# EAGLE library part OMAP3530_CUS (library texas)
OMAP 3530/25 Applications Processor 600-MHz ARM Cortex?-A8 Core Auto generated by make-symbol-device-package-bsdl.ulp Rev. 23 Source: sprm314.bsd
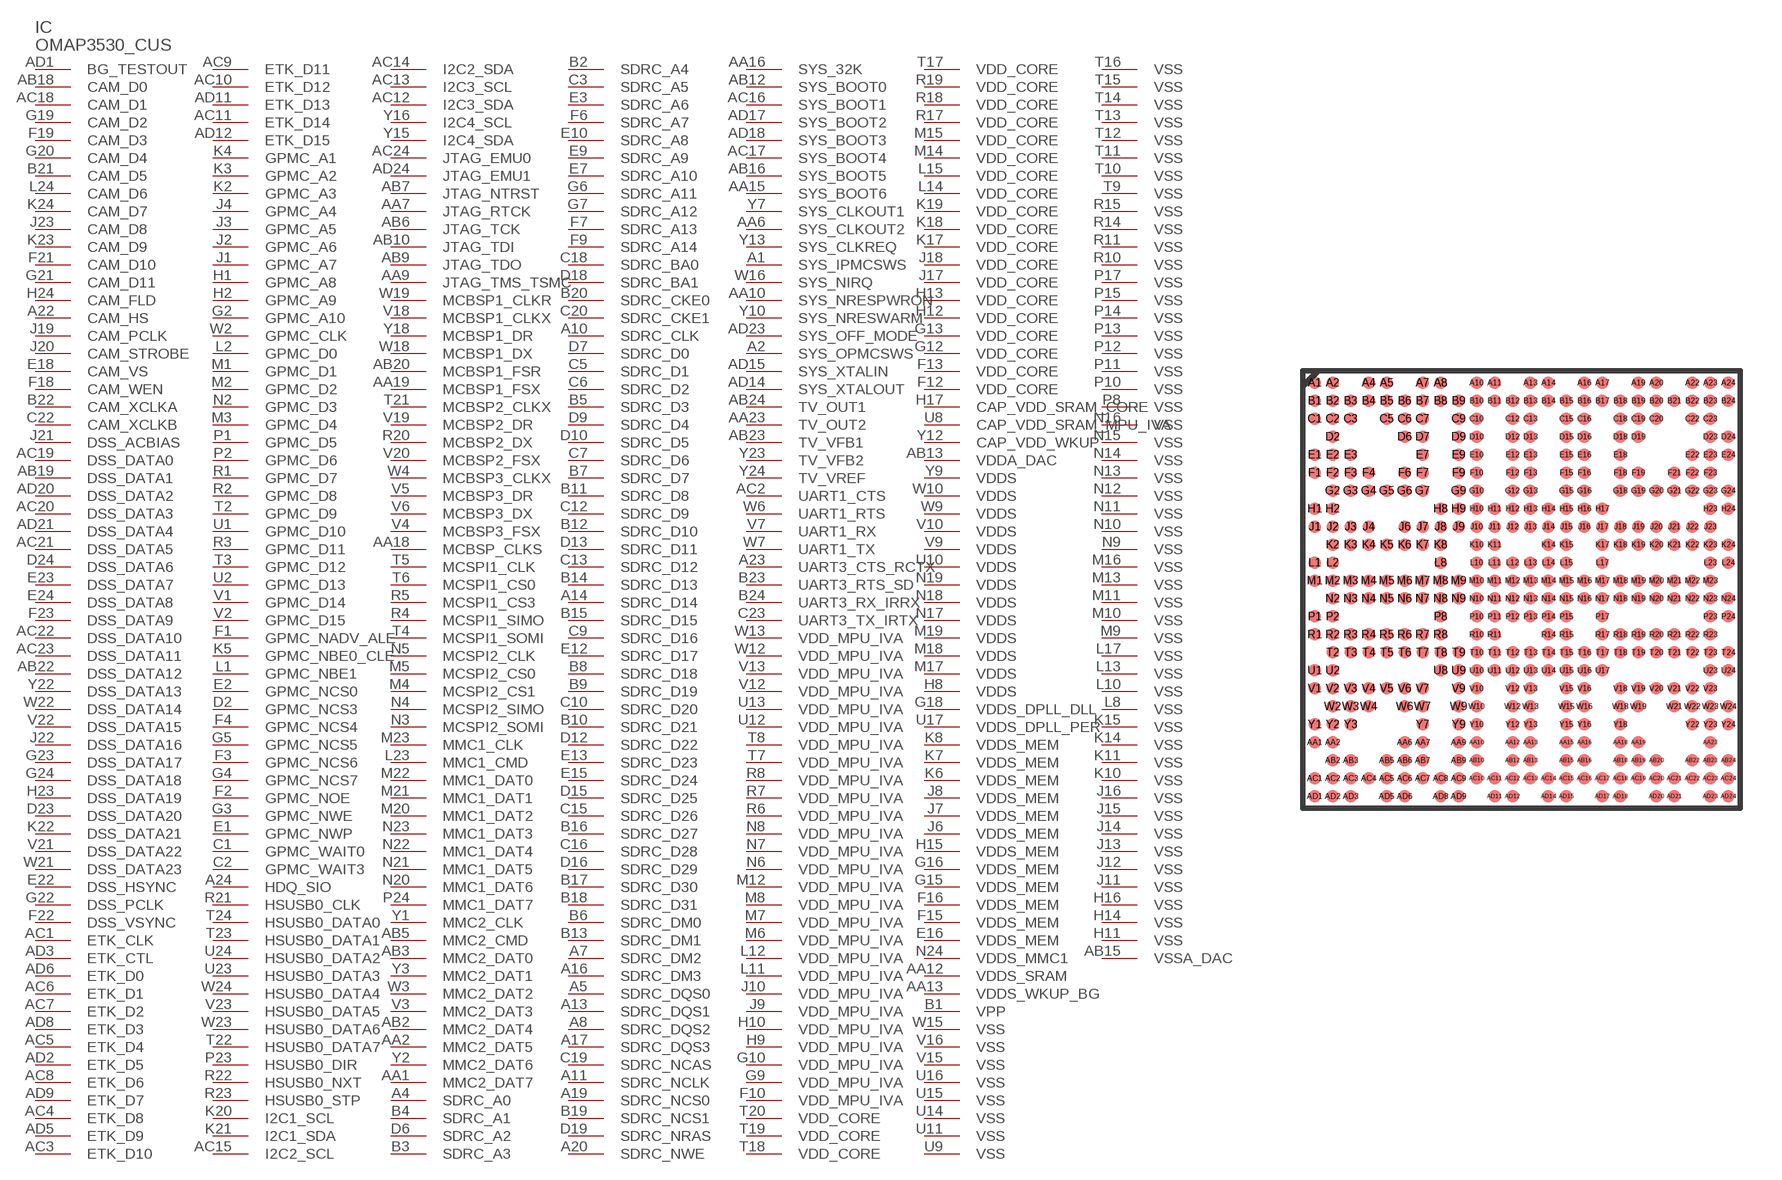
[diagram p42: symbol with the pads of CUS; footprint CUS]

Designator prefix IC

## OMAP3530_CUS (OC_FARNELL: unknown; OC_NEWARK: unknown)  [CUS]
A1  SYS_IPMCSWS  pas
A2  SYS_OPMCSWS  pas
A4  SDRC_A0  out
A5  SDRC_DQS0  pas
A7  SDRC_DM2  out
A8  SDRC_DQS2  pas
A10  SDRC_CLK  pas
A11  SDRC_NCLK  pas
A13  SDRC_DQS1  pas
A14  SDRC_D14
A16  SDRC_DM3  out
A17  SDRC_DQS3  pas
A19  SDRC_NCS0  out
A20  SDRC_NWE  out
A22  CAM_HS
A23  UART3_CTS_RCTX
A24  HDQ_SIO
AA1  MMC2_DAT7
AA2  MMC2_DAT5
AA6  SYS_CLKOUT2
AA7  JTAG_RTCK  pas
AA9  JTAG_TMS_TSMC  in
AA10  SYS_NRESPWRON  pas
AA12  VDDS_SRAM  pwr
AA13  VDDS_WKUP_BG  pwr
AA15  SYS_BOOT6
AA16  SYS_32K  pas
AA18  MCBSP_CLKS
AA19  MCBSP1_FSX
AA23  TV_OUT2  pas
AB2  MMC2_DAT4
AB3  MMC2_DAT0
AB5  MMC2_CMD
AB6  JTAG_TCK  in
AB7  JTAG_NTRST  in
AB9  JTAG_TDO  out
AB10  JTAG_TDI  in
AB12  SYS_BOOT0
AB13  VDDA_DAC  pwr
AB15  VSSA_DAC  pwr
AB16  SYS_BOOT5
AB18  CAM_D0
AB19  DSS_DATA1
AB20  MCBSP1_FSR
AB22  DSS_DATA12
AB23  TV_VFB1  pas
AB24  TV_OUT1  pas
AC1  ETK_CLK
AC2  UART1_CTS
AC3  ETK_D10
AC4  ETK_D8
AC5  ETK_D4
AC6  ETK_D1
AC7  ETK_D2
AC8  ETK_D6
AC9  ETK_D11
AC10  ETK_D12
AC11  ETK_D14
AC12  I2C3_SDA
AC13  I2C3_SCL
AC14  I2C2_SDA
AC15  I2C2_SCL
AC16  SYS_BOOT1
AC17  SYS_BOOT4
AC18  CAM_D1
AC19  DSS_DATA0
AC20  DSS_DATA3
AC21  DSS_DATA5
AC22  DSS_DATA10
AC23  DSS_DATA11
AC24  JTAG_EMU0  pas
AD1  BG_TESTOUT
AD2  ETK_D5
AD3  ETK_CTL
AD5  ETK_D9
AD6  ETK_D0
AD8  ETK_D3
AD9  ETK_D7
AD11  ETK_D13
AD12  ETK_D15
AD14  SYS_XTALOUT  pas
AD15  SYS_XTALIN  pas
AD17  SYS_BOOT2
AD18  SYS_BOOT3
AD20  DSS_DATA2
AD21  DSS_DATA4
AD23  SYS_OFF_MODE
AD24  JTAG_EMU1  pas
B1  VPP  pas
B2  SDRC_A4  out
B3  SDRC_A3  out
B4  SDRC_A1  out
B5  SDRC_D3
B6  SDRC_DM0  out
B7  SDRC_D7
B8  SDRC_D18
B9  SDRC_D19
B10  SDRC_D21
B11  SDRC_D8
B12  SDRC_D10
B13  SDRC_DM1  out
B14  SDRC_D13
B15  SDRC_D15
B16  SDRC_D27
B17  SDRC_D30
B18  SDRC_D31
B19  SDRC_NCS1  out
B20  SDRC_CKE0  out
B21  CAM_D5
B22  CAM_XCLKA
B23  UART3_RTS_SD
B24  UART3_RX_IRRX
C1  GPMC_WAIT0  in
C2  GPMC_WAIT3
C3  SDRC_A5  out
C5  SDRC_D1
C6  SDRC_D2
C7  SDRC_D6
C9  SDRC_D16
C10  SDRC_D20
C12  SDRC_D9
C13  SDRC_D12
C15  SDRC_D26
C16  SDRC_D28
C18  SDRC_BA0  out
C19  SDRC_NCAS  out
C20  SDRC_CKE1  out
C22  CAM_XCLKB
C23  UART3_TX_IRTX
D2  GPMC_NCS3
D6  SDRC_A2  out
D7  SDRC_D0
D9  SDRC_D4
D10  SDRC_D5
D12  SDRC_D22
D13  SDRC_D11
D15  SDRC_D25
D16  SDRC_D29
D18  SDRC_BA1  out
D19  SDRC_NRAS  out
D23  DSS_DATA20
D24  DSS_DATA6
E1  GPMC_NWP
E2  GPMC_NCS0  out
E3  SDRC_A6  out
E7  SDRC_A10  out
E9  SDRC_A9  out
E10  SDRC_A8  out
E12  SDRC_D17
E13  SDRC_D23
E15  SDRC_D24
E16  VDDS_MEM  pwr
E18  CAM_VS
E22  DSS_HSYNC
E23  DSS_DATA7
E24  DSS_DATA8
F1  GPMC_NADV_ALE  out
F2  GPMC_NOE  out
F3  GPMC_NCS6
F4  GPMC_NCS4
F6  SDRC_A7  out
F7  SDRC_A13  out
F9  SDRC_A14  out
F10  VDD_MPU_IVA  pwr
F12  VDD_CORE  pwr
F13  VDD_CORE  pwr
F15  VDDS_MEM  pwr
F16  VDDS_MEM  pwr
F18  CAM_WEN
F19  CAM_D3
F21  CAM_D10
F22  DSS_VSYNC
F23  DSS_DATA9
G2  GPMC_A10
G3  GPMC_NWE  out
G4  GPMC_NCS7
G5  GPMC_NCS5
G6  SDRC_A11  out
G7  SDRC_A12  out
G9  VDD_MPU_IVA  pwr
G10  VDD_MPU_IVA  pwr
G12  VDD_CORE  pwr
G13  VDD_CORE  pwr
G15  VDDS_MEM  pwr
G16  VDDS_MEM  pwr
G18  VDDS_DPLL_DLL  pwr
G19  CAM_D2
G20  CAM_D4
G21  CAM_D11
G22  DSS_PCLK
G23  DSS_DATA17
G24  DSS_DATA18
H1  GPMC_A8
H2  GPMC_A9
H8  VDDS  pwr
H9  VDD_MPU_IVA  pwr
H10  VDD_MPU_IVA  pwr
H11  VSS  pwr
H12  VDD_CORE  pwr
H13  VDD_CORE  pwr
H14  VSS  pwr
H15  VDDS_MEM  pwr
H16  VSS  pwr
H17  CAP_VDD_SRAM_CORE  pwr
H23  DSS_DATA19
H24  CAM_FLD
J1  GPMC_A7
J2  GPMC_A6
J3  GPMC_A5
J4  GPMC_A4
J6  VDDS_MEM  pwr
J7  VDDS_MEM  pwr
J8  VDDS_MEM  pwr
J9  VDD_MPU_IVA  pwr
J10  VDD_MPU_IVA  pwr
J11  VSS  pwr
J12  VSS  pwr
J13  VSS  pwr
J14  VSS  pwr
J15  VSS  pwr
J16  VSS  pwr
J17  VDD_CORE  pwr
J18  VDD_CORE  pwr
J19  CAM_PCLK
J20  CAM_STROBE
J21  DSS_ACBIAS
J22  DSS_DATA16
J23  CAM_D8
K2  GPMC_A3
K3  GPMC_A2
K4  GPMC_A1
K5  GPMC_NBE0_CLE
K6  VDDS_MEM  pwr
K7  VDDS_MEM  pwr
K8  VDDS_MEM  pwr
K10  VSS  pwr
K11  VSS  pwr
K14  VSS  pwr
K15  VSS  pwr
K17  VDD_CORE  pwr
K18  VDD_CORE  pwr
K19  VDD_CORE  pwr
K20  I2C1_SCL
K21  I2C1_SDA
K22  DSS_DATA21
K23  CAM_D9
K24  CAM_D7
L1  GPMC_NBE1
L2  GPMC_D0
L8  VSS  pwr
L10  VSS  pwr
L11  VDD_MPU_IVA  pwr
L12  VDD_MPU_IVA  pwr
L13  VSS  pwr
L14  VDD_CORE  pwr
L15  VDD_CORE  pwr
L17  VSS  pwr
L23  MMC1_CMD
L24  CAM_D6
M1  GPMC_D1
M2  GPMC_D2
M3  GPMC_D4
M4  MCSPI2_CS1
M5  MCSPI2_CS0
M6  VDD_MPU_IVA  pwr
M7  VDD_MPU_IVA  pwr
M8  VDD_MPU_IVA  pwr
M9  VSS  pwr
M10  VSS  pwr
M11  VSS  pwr
M12  VDD_MPU_IVA  pwr
M13  VSS  pwr
M14  VDD_CORE  pwr
M15  VDD_CORE  pwr
M16  VSS  pwr
M17  VDDS  pwr
M18  VDDS  pwr
M19  VDDS  pwr
M20  MMC1_DAT2
M21  MMC1_DAT1
M22  MMC1_DAT0
M23  MMC1_CLK
N2  GPMC_D3
N3  MCSPI2_SOMI
N4  MCSPI2_SIMO
N5  MCSPI2_CLK
N6  VDD_MPU_IVA  pwr
N7  VDD_MPU_IVA  pwr
N8  VDD_MPU_IVA  pwr
N9  VSS  pwr
N10  VSS  pwr
N11  VSS  pwr
N12  VSS  pwr
N13  VSS  pwr
N14  VSS  pwr
N15  VSS  pwr
N16  VSS  pwr
N17  VDDS  pwr
N18  VDDS  pwr
N19  VDDS  pwr
N20  MMC1_DAT6
N21  MMC1_DAT5
N22  MMC1_DAT4
N23  MMC1_DAT3
N24  VDDS_MMC1  pwr
P1  GPMC_D5
P2  GPMC_D6
P8  VSS  pwr
P10  VSS  pwr
P11  VSS  pwr
P12  VSS  pwr
P13  VSS  pwr
P14  VSS  pwr
P15  VSS  pwr
P17  VSS  pwr
P23  HSUSB0_DIR
P24  MMC1_DAT7
R1  GPMC_D7
R2  GPMC_D8
R3  GPMC_D11
R4  MCSPI1_SIMO
R5  MCSPI1_CS3
R6  VDD_MPU_IVA  pwr
R7  VDD_MPU_IVA  pwr
R8  VDD_MPU_IVA  pwr
R10  VSS  pwr
R11  VSS  pwr
R14  VSS  pwr
R15  VSS  pwr
R17  VDD_CORE  pwr
R18  VDD_CORE  pwr
R19  VDD_CORE  pwr
R20  MCBSP2_DX
R21  HSUSB0_CLK
R22  HSUSB0_NXT
R23  HSUSB0_STP
T2  GPMC_D9
T3  GPMC_D12
T4  MCSPI1_SOMI
T5  MCSPI1_CLK
T6  MCSPI1_CS0
T7  VDD_MPU_IVA  pwr
T8  VDD_MPU_IVA  pwr
T9  VSS  pwr
T10  VSS  pwr
T11  VSS  pwr
T12  VSS  pwr
T13  VSS  pwr
T14  VSS  pwr
T15  VSS  pwr
T16  VSS  pwr
T17  VDD_CORE  pwr
T18  VDD_CORE  pwr
T19  VDD_CORE  pwr
T20  VDD_CORE  pwr
T21  MCBSP2_CLKX
T22  HSUSB0_DATA7
T23  HSUSB0_DATA1
T24  HSUSB0_DATA0
U1  GPMC_D10
U2  GPMC_D13
U8  CAP_VDD_SRAM_MPU_IVA  pwr
U9  VSS  pwr
U10  VDDS  pwr
U11  VSS  pwr
U12  VDD_MPU_IVA  pwr
U13  VDD_MPU_IVA  pwr
U14  VSS  pwr
U15  VSS  pwr
U16  VSS  pwr
U17  VDDS_DPLL_PER  pwr
U23  HSUSB0_DATA3
U24  HSUSB0_DATA2
V1  GPMC_D14
V2  GPMC_D15
V3  MMC2_DAT3
V4  MCBSP3_FSX
V5  MCBSP3_DR
V6  MCBSP3_DX
V7  UART1_RX
V9  VDDS  pwr
V10  VDDS  pwr
V12  VDD_MPU_IVA  pwr
V13  VDD_MPU_IVA  pwr
V15  VSS  pwr
V16  VSS  pwr
V18  MCBSP1_CLKX
V19  MCBSP2_DR
V20  MCBSP2_FSX
V21  DSS_DATA22
V22  DSS_DATA15
V23  HSUSB0_DATA5
W2  GPMC_CLK
W3  MMC2_DAT2
W4  MCBSP3_CLKX
W6  UART1_RTS
W7  UART1_TX
W9  VDDS  pwr
W10  VDDS  pwr
W12  VDD_MPU_IVA  pwr
W13  VDD_MPU_IVA  pwr
W15  VSS  pwr
W16  SYS_NIRQ
W18  MCBSP1_DX
W19  MCBSP1_CLKR
W21  DSS_DATA23
W22  DSS_DATA14
W23  HSUSB0_DATA6
W24  HSUSB0_DATA4
Y1  MMC2_CLK
Y2  MMC2_DAT6
Y3  MMC2_DAT1
Y7  SYS_CLKOUT1
Y9  VDDS  pwr
Y10  SYS_NRESWARM  pas
Y12  CAP_VDD_WKUP  pwr
Y13  SYS_CLKREQ
Y15  I2C4_SDA
Y16  I2C4_SCL
Y18  MCBSP1_DR
Y22  DSS_DATA13
Y23  TV_VFB2  pas
Y24  TV_VREF  pas

## Footprint CUS (pad centres in mm)
CUS (S-PBGA-N423) Auto generated by make-symbol-device-package-bsdl.ulp Rev. 23 Source: sprm314.bsd
smd 0.45 x 0.45: A1 -7.475,7.475; A2 -6.825,7.475; A4 -5.525,7.475; A5 -4.875,7.475; A7 -3.575,7.475; A8 -2.925,7.475; A10 -1.625,7.475; A11 -0.975,7.475; A13 0.325,7.475; A14 0.975,7.475; A16 2.275,7.475; A17 2.925,7.475; A19 4.225,7.475; A20 4.875,7.475; A22 6.175,7.475; A23 6.825,7.475; A24 7.475,7.475; AA1 -7.475,-5.525; AA2 -6.825,-5.525; AA6 -4.225,-5.525; AA7 -3.575,-5.525; AA9 -2.275,-5.525; AA10 -1.625,-5.525; AA12 -0.325,-5.525; AA13 0.325,-5.525; AA15 1.625,-5.525; AA16 2.275,-5.525; AA18 3.575,-5.525; AA19 4.225,-5.525; AA23 6.825,-5.525; AB2 -6.825,-6.175; AB3 -6.175,-6.175; AB5 -4.875,-6.175; AB6 -4.225,-6.175; AB7 -3.575,-6.175; AB9 -2.275,-6.175; AB10 -1.625,-6.175; AB12 -0.325,-6.175; AB13 0.325,-6.175; AB15 1.625,-6.175; AB16 2.275,-6.175; AB18 3.575,-6.175; AB19 4.225,-6.175; AB20 4.875,-6.175; AB22 6.175,-6.175; AB23 6.825,-6.175; AB24 7.475,-6.175; AC1 -7.475,-6.825; AC2 -6.825,-6.825; AC3 -6.175,-6.825; AC4 -5.525,-6.825; AC5 -4.875,-6.825; AC6 -4.225,-6.825; AC7 -3.575,-6.825; AC8 -2.925,-6.825; AC9 -2.275,-6.825; AC10 -1.625,-6.825; AC11 -0.975,-6.825; AC12 -0.325,-6.825; AC13 0.325,-6.825; AC14 0.975,-6.825; AC15 1.625,-6.825; AC16 2.275,-6.825; AC17 2.925,-6.825; AC18 3.575,-6.825; AC19 4.225,-6.825; AC20 4.875,-6.825; AC21 5.525,-6.825; AC22 6.175,-6.825; AC23 6.825,-6.825; AC24 7.475,-6.825; AD1 -7.475,-7.475; AD2 -6.825,-7.475; AD3 -6.175,-7.475; AD5 -4.875,-7.475; AD6 -4.225,-7.475; AD8 -2.925,-7.475; AD9 -2.275,-7.475; AD11 -0.975,-7.475; AD12 -0.325,-7.475; AD14 0.975,-7.475; AD15 1.625,-7.475; AD17 2.925,-7.475; AD18 3.575,-7.475; AD20 4.875,-7.475; AD21 5.525,-7.475; AD23 6.825,-7.475; AD24 7.475,-7.475; B1 -7.475,6.825; B2 -6.825,6.825; B3 -6.175,6.825; B4 -5.525,6.825; B5 -4.875,6.825; B6 -4.225,6.825; B7 -3.575,6.825; B8 -2.925,6.825; B9 -2.275,6.825; B10 -1.625,6.825; B11 -0.975,6.825; B12 -0.325,6.825; B13 0.325,6.825; B14 0.975,6.825; B15 1.625,6.825; B16 2.275,6.825; B17 2.925,6.825; B18 3.575,6.825; B19 4.225,6.825; B20 4.875,6.825; B21 5.525,6.825; B22 6.175,6.825; B23 6.825,6.825; B24 7.475,6.825; C1 -7.475,6.175; C2 -6.825,6.175; C3 -6.175,6.175; C5 -4.875,6.175; C6 -4.225,6.175; C7 -3.575,6.175; C9 -2.275,6.175; C10 -1.625,6.175; C12 -0.325,6.175; C13 0.325,6.175; C15 1.625,6.175; C16 2.275,6.175; C18 3.575,6.175; C19 4.225,6.175; C20 4.875,6.175; C22 6.175,6.175; C23 6.825,6.175; D2 -6.825,5.525; D6 -4.225,5.525; D7 -3.575,5.525; D9 -2.275,5.525; D10 -1.625,5.525; D12 -0.325,5.525; D13 0.325,5.525; D15 1.625,5.525; D16 2.275,5.525; D18 3.575,5.525; D19 4.225,5.525; D23 6.825,5.525; D24 7.475,5.525; E1 -7.475,4.875; E2 -6.825,4.875; E3 -6.175,4.875; E7 -3.575,4.875; E9 -2.275,4.875; E10 -1.625,4.875; E12 -0.325,4.875; E13 0.325,4.875; E15 1.625,4.875; E16 2.275,4.875; E18 3.575,4.875; E22 6.175,4.875; E23 6.825,4.875; E24 7.475,4.875; F1 -7.475,4.225; F2 -6.825,4.225; F3 -6.175,4.225; F4 -5.525,4.225; F6 -4.225,4.225; F7 -3.575,4.225; F9 -2.275,4.225; F10 -1.625,4.225; F12 -0.325,4.225; F13 0.325,4.225; F15 1.625,4.225; F16 2.275,4.225; F18 3.575,4.225; F19 4.225,4.225; F21 5.525,4.225; F22 6.175,4.225; F23 6.825,4.225; G2 -6.825,3.575; G3 -6.175,3.575; G4 -5.525,3.575; G5 -4.875,3.575; G6 -4.225,3.575; G7 -3.575,3.575; G9 -2.275,3.575; G10 -1.625,3.575; G12 -0.325,3.575; G13 0.325,3.575; G15 1.625,3.575; G16 2.275,3.575; G18 3.575,3.575; G19 4.225,3.575; G20 4.875,3.575; G21 5.525,3.575; G22 6.175,3.575; G23 6.825,3.575; G24 7.475,3.575; H1 -7.475,2.925; H2 -6.825,2.925; H8 -2.925,2.925; H9 -2.275,2.925; H10 -1.625,2.925; H11 -0.975,2.925; H12 -0.325,2.925; H13 0.325,2.925; H14 0.975,2.925; H15 1.625,2.925; H16 2.275,2.925; H17 2.925,2.925; H23 6.825,2.925; H24 7.475,2.925; J1 -7.475,2.275; J2 -6.825,2.275; J3 -6.175,2.275; J4 -5.525,2.275; J6 -4.225,2.275; J7 -3.575,2.275; J8 -2.925,2.275; J9 -2.275,2.275; J10 -1.625,2.275; J11 -0.975,2.275; J12 -0.325,2.275; J13 0.325,2.275; J14 0.975,2.275; J15 1.625,2.275; J16 2.275,2.275; J17 2.925,2.275; J18 3.575,2.275; J19 4.225,2.275; J20 4.875,2.275; J21 5.525,2.275; J22 6.175,2.275; J23 6.825,2.275; K2 -6.825,1.625; K3 -6.175,1.625; K4 -5.525,1.625; K5 -4.875,1.625; K6 -4.225,1.625; K7 -3.575,1.625; K8 -2.925,1.625; K10 -1.625,1.625; K11 -0.975,1.625; K14 0.975,1.625; K15 1.625,1.625; K17 2.925,1.625; K18 3.575,1.625; K19 4.225,1.625; K20 4.875,1.625; K21 5.525,1.625; K22 6.175,1.625; K23 6.825,1.625; K24 7.475,1.625; L1 -7.475,0.975; L2 -6.825,0.975; L8 -2.925,0.975; L10 -1.625,0.975; L11 -0.975,0.975; L12 -0.325,0.975; L13 0.325,0.975; L14 0.975,0.975; L15 1.625,0.975; L17 2.925,0.975; L23 6.825,0.975; L24 7.475,0.975; M1 -7.475,0.325; M2 -6.825,0.325; M3 -6.175,0.325; M4 -5.525,0.325; M5 -4.875,0.325; M6 -4.225,0.325; M7 -3.575,0.325; M8 -2.925,0.325; M9 -2.275,0.325; M10 -1.625,0.325; M11 -0.975,0.325; M12 -0.325,0.325; M13 0.325,0.325; M14 0.975,0.325; M15 1.625,0.325; M16 2.275,0.325; M17 2.925,0.325; M18 3.575,0.325; M19 4.225,0.325; M20 4.875,0.325; M21 5.525,0.325; M22 6.175,0.325; M23 6.825,0.325; N2 -6.825,-0.325; N3 -6.175,-0.325; N4 -5.525,-0.325; N5 -4.875,-0.325; N6 -4.225,-0.325; N7 -3.575,-0.325; N8 -2.925,-0.325; N9 -2.275,-0.325; N10 -1.625,-0.325; N11 -0.975,-0.325; N12 -0.325,-0.325; N13 0.325,-0.325; N14 0.975,-0.325; N15 1.625,-0.325; N16 2.275,-0.325; N17 2.925,-0.325; N18 3.575,-0.325; N19 4.225,-0.325; N20 4.875,-0.325; N21 5.525,-0.325; N22 6.175,-0.325; N23 6.825,-0.325; N24 7.475,-0.325; P1 -7.475,-0.975; P2 -6.825,-0.975; P8 -2.925,-0.975; P10 -1.625,-0.975; P11 -0.975,-0.975; P12 -0.325,-0.975; P13 0.325,-0.975; P14 0.975,-0.975; P15 1.625,-0.975; P17 2.925,-0.975; P23 6.825,-0.975; P24 7.475,-0.975; R1 -7.475,-1.625; R2 -6.825,-1.625; R3 -6.175,-1.625; R4 -5.525,-1.625; R5 -4.875,-1.625; R6 -4.225,-1.625; R7 -3.575,-1.625; R8 -2.925,-1.625; R10 -1.625,-1.625; R11 -0.975,-1.625; R14 0.975,-1.625; R15 1.625,-1.625; R17 2.925,-1.625; R18 3.575,-1.625; R19 4.225,-1.625; R20 4.875,-1.625; R21 5.525,-1.625; R22 6.175,-1.625; R23 6.825,-1.625; T2 -6.825,-2.275; T3 -6.175,-2.275; T4 -5.525,-2.275; T5 -4.875,-2.275; T6 -4.225,-2.275; T7 -3.575,-2.275; T8 -2.925,-2.275; T9 -2.275,-2.275; T10 -1.625,-2.275; T11 -0.975,-2.275; T12 -0.325,-2.275; T13 0.325,-2.275; T14 0.975,-2.275; T15 1.625,-2.275; T16 2.275,-2.275; T17 2.925,-2.275; T18 3.575,-2.275; T19 4.225,-2.275; T20 4.875,-2.275; T21 5.525,-2.275; T22 6.175,-2.275; T23 6.825,-2.275; T24 7.475,-2.275; U1 -7.475,-2.925; U2 -6.825,-2.925; U8 -2.925,-2.925; U9 -2.275,-2.925; U10 -1.625,-2.925; U11 -0.975,-2.925; U12 -0.325,-2.925; U13 0.325,-2.925; U14 0.975,-2.925; U15 1.625,-2.925; U16 2.275,-2.925; U17 2.925,-2.925; U23 6.825,-2.925; U24 7.475,-2.925; V1 -7.475,-3.575; V2 -6.825,-3.575; V3 -6.175,-3.575; V4 -5.525,-3.575; V5 -4.875,-3.575; V6 -4.225,-3.575; V7 -3.575,-3.575; V9 -2.275,-3.575; V10 -1.625,-3.575; V12 -0.325,-3.575; V13 0.325,-3.575; V15 1.625,-3.575; V16 2.275,-3.575; V18 3.575,-3.575; V19 4.225,-3.575; V20 4.875,-3.575; V21 5.525,-3.575; V22 6.175,-3.575; V23 6.825,-3.575; W2 -6.825,-4.225; W3 -6.175,-4.225; W4 -5.525,-4.225; W6 -4.225,-4.225; W7 -3.575,-4.225; W9 -2.275,-4.225; W10 -1.625,-4.225; W12 -0.325,-4.225; W13 0.325,-4.225; W15 1.625,-4.225; W16 2.275,-4.225; W18 3.575,-4.225; W19 4.225,-4.225; W21 5.525,-4.225; W22 6.175,-4.225; W23 6.825,-4.225; W24 7.475,-4.225; Y1 -7.475,-4.875; Y2 -6.825,-4.875; Y3 -6.175,-4.875; Y7 -3.575,-4.875; Y9 -2.275,-4.875; Y10 -1.625,-4.875; Y12 -0.325,-4.875; Y13 0.325,-4.875; Y15 1.625,-4.875; Y16 2.275,-4.875; Y18 3.575,-4.875; Y22 6.175,-4.875; Y23 6.825,-4.875; Y24 7.475,-4.875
